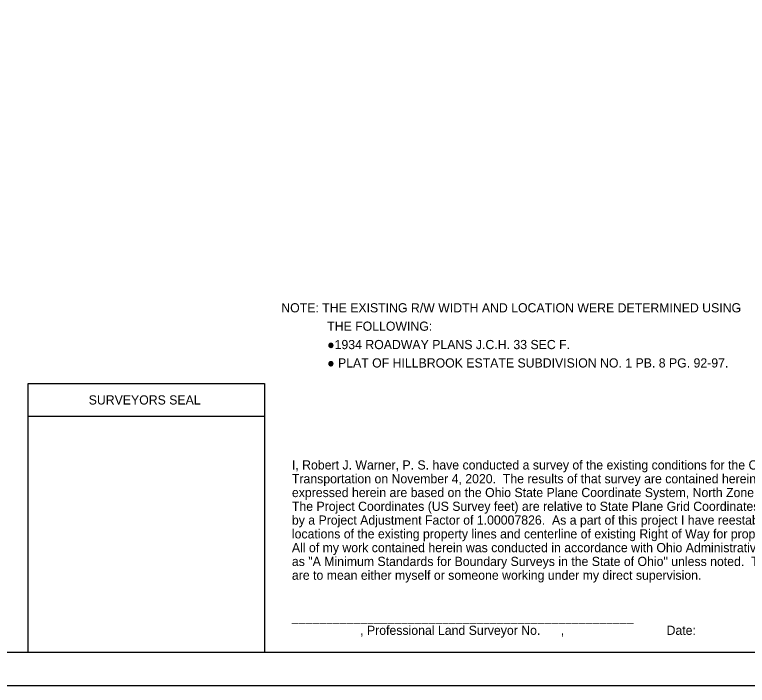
# Model space of a CAD drawing. Extents: x -7 to 3400, y -220 to 22.
# Drawn here: x 17.08 to 28.25, y 0 to 10.22 of the extents above; entities that cross this region are included whole.
import ezdxf

# ---------------------------------------------------------------- set-up
doc = ezdxf.new("R2010")
doc.units = 0
for name, color, linetype in [('SH_Border', 7, 'Continuous'), ('SH_Cut_Line', 7, 'Continuous'), ('SH_Data', 7, 'Continuous'), ('SH_Text', 7, 'Continuous')]:
    doc.layers.add(name, color=color, linetype=linetype)

msp = doc.modelspace()

# ---------------------------------------------------------------- linework, layer by layer
at = {"layer": 'SH_Border'}
msp.add_lwpolyline([(1.5, 21.5), (33.5, 21.5), (33.5, 0.5), (1.5, 0.5)], close=True, dxfattribs=at)
at = {"layer": 'SH_Cut_Line'}
msp.add_lwpolyline([(0, 0), (34, 0), (34, 22), (0, 22)], close=True, dxfattribs=at)
at = {"layer": 'SH_Data'}
msp.add_line((17.288, 4.1), (20.888, 4.1), dxfattribs=at)
msp.add_lwpolyline([(17.288, 4.6), (20.888, 4.6), (20.888, 0.5), (17.288, 0.5)], close=True, dxfattribs=at)

# ---------------------------------------------------------------- texts
msp.add_text('SURVEYORS SEAL', height=0.14, dxfattribs=at).set_placement((18.209, 4.28))
at = {"layer": 'SH_Text'}
for s, p in [('NOTE: THE EXISTING R/W WIDTH AND LOCATION WERE DETERMINED USING ', (21.145, 5.684)), ('THE FOLLOWING:', (21.845, 5.404)), ('●1934 ROADWAY PLANS J.C.H. 33 SEC F.', (21.845, 5.124)), ('● PLAT OF HILLBROOK ESTATE SUBDIVISION NO. 1 PB. 8 PG. 92-97.', (21.845, 4.844)), ('I, Robert J. Warner, P. S. have conducted a survey of the existing conditions for the Ohio Department of', (21.307, 3.289)), ('Transportation on November 4, 2020.  The results of that survey are contained herein.  The horizontal coordinates', (21.307, 3.079)), ('expressed herein are based on the Ohio State Plane Coordinate System, North Zone on NAD 83 (2011) datum.', (21.307, 2.869)), ('The Project Coordinates (US Survey feet) are relative to State Plane Grid Coordinates (US Survey feet)', (21.307, 2.659)), ('by a Project Adjustment Factor of 1.00007826.  As a part of this project I have reestablished the', (21.307, 2.449)), ('locations of the existing property lines and centerline of existing Right of Way for property takes contained herein.  ', (21.307, 2.239)), ('All of my work contained herein was conducted in accordance with Ohio Administrative Code 4733-37 commonly known', (21.307, 2.029)), ('as "A Minimum Standards for Boundary Surveys in the State of Ohio" unless noted.  The words I and my as used herein', (21.307, 1.819)), ('are to mean either myself or someone working under my direct supervision.', (21.307, 1.609)), ('__________________________________________________', (21.307, 0.979)), ('                    , Professional Land Surveyor No.      ,                              Date:                ', (21.307, 0.769))]:
    msp.add_text(s, height=0.14, dxfattribs=at).set_placement(p)

doc.saveas('drawing.dxf')
